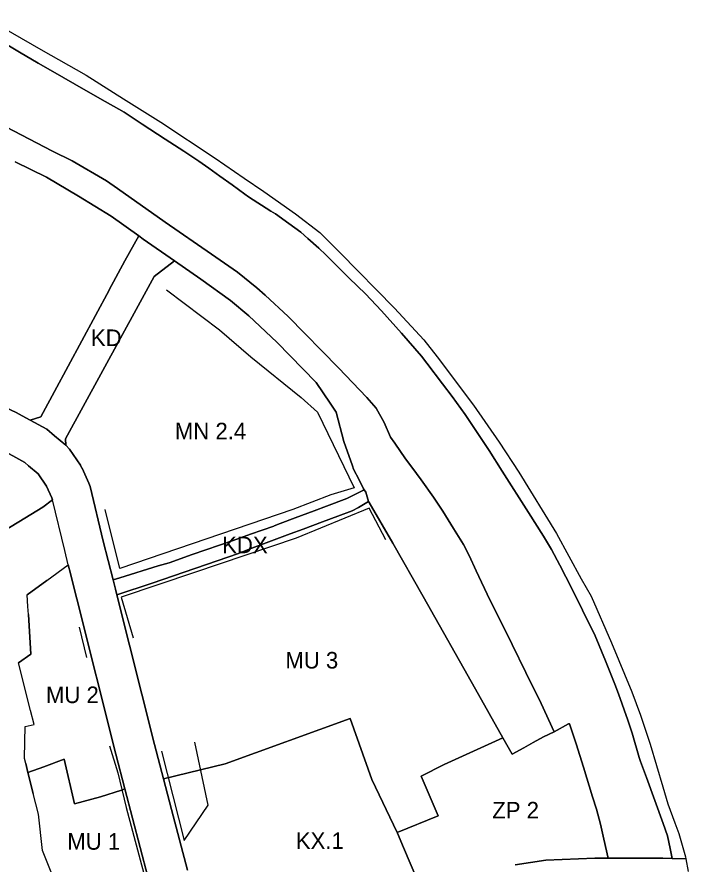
# Model space of a CAD drawing. Extents: x 7421359 to 7422386, y 5546414 to 5547388.
# Drawn here: x 7422151.6 to 7422354.4, y 5546861.7 to 5547117.5 of the extents above; entities that cross this region are included whole.
import ezdxf

# ---------------------------------------------------------------- set-up
doc = ezdxf.new("R2010")
doc.units = 0
for name, color, linetype in [('linie_rozgraniczajace', 7, 'Continuous'), ('linie_zabudowy', 7, 'Continuous'), ('oznaczenia_przeznaczen', 7, 'Continuous')]:
    doc.layers.add(name, color=color, linetype=linetype)

msp = doc.modelspace()

# ---------------------------------------------------------------- linework, layer by layer
at = {"layer": 'linie_rozgraniczajace'}
for points in [[(7422141.61, 5547117.54), (7422158.89, 5547107.72), (7422172.57, 5547099.93), (7422183.85, 5547092.84), (7422195.13, 5547085.76), (7422211.52, 5547074.84), (7422220.3, 5547068.87), (7422226.23, 5547064.84), (7422235.77, 5547058.08), (7422243.15, 5547052.42), (7422249.29, 5547046.25), (7422265.72, 5547029.57), (7422274.58, 5547020), (7422278.63, 5547014.87), (7422289.62, 5547000.29), (7422297.35, 5546989.09), (7422303.28, 5546980.06), (7422314.69, 5546961.52), (7422322.13, 5546947.79), (7422325.12, 5546942.62), (7422331.32, 5546928.5), (7422337.48, 5546913.66), (7422340.02, 5546906.62), (7422342.95, 5546897.93), (7422346.79, 5546884.98), (7422348.32, 5546879.88), (7422350.41, 5546874.14), (7422351.6, 5546870.88), (7422353.67, 5546863.88), (7422353.77, 5546863.31), (7422349.65, 5546863.38), (7422349.07, 5546866.36), (7422348.22, 5546870.17), (7422346.88, 5546873.99), (7422341.89, 5546887.8), (7422340.03, 5546892.64), (7422339.66, 5546893.83), (7422337.55, 5546901.2), (7422336.21, 5546905.11), (7422333.43, 5546913.11), (7422332.29, 5546916.03), (7422329.53, 5546923.07), (7422326.39, 5546930.64), (7422322.58, 5546938.38), (7422319.35, 5546944.93), (7422315.72, 5546952.01), (7422313.17, 5546956.68), (7422310.71, 5546960.77), (7422306.23, 5546967.89), (7422298.29, 5546980.38), (7422294.33, 5546986.61), (7422290.15, 5546992.91), (7422287.1, 5546997.42), (7422283.17, 5547002.86), (7422280.26, 5547006.75), (7422275.51, 5547013), (7422273.89, 5547015.11), (7422267.89, 5547022.03), (7422261.82, 5547028.73), (7422256.98, 5547033.91), (7422252.04, 5547038.69), (7422249.33, 5547041.36)], [(7422145.42, 5547110.99), (7422152.45, 5547106.92), (7422158.09, 5547103.62), (7422162.48, 5547101.09), (7422169.17, 5547097.24), (7422176.67, 5547092.95), (7422184.09, 5547088.74), (7422189.52, 5547085.16), (7422196.47, 5547080.62), (7422202.08, 5547076.96), (7422206.58, 5547073.97), (7422209.63, 5547071.91), (7422212.98, 5547069.5), (7422216.65, 5547066.82), (7422220.52, 5547064.06), (7422221.66, 5547063.22), (7422228.37, 5547058.91), (7422229.75, 5547058.04), (7422233.76, 5547055.14), (7422237.39, 5547052.56), (7422239.55, 5547050.65), (7422242.91, 5547047.73), (7422244.94, 5547045.73), (7422249.33, 5547041.36), (7422252.04, 5547038.69), (7422256.98, 5547033.91), (7422261.82, 5547028.73), (7422267.89, 5547022.03), (7422273.89, 5547015.11), (7422275.51, 5547013), (7422280.26, 5547006.75), (7422283.17, 5547002.86), (7422287.1, 5546997.42), (7422290.15, 5546992.91), (7422294.33, 5546986.61), (7422298.29, 5546980.38), (7422306.23, 5546967.89), (7422310.71, 5546960.77), (7422313.17, 5546956.68), (7422315.72, 5546952.01), (7422319.35, 5546944.93), (7422322.58, 5546938.38), (7422326.39, 5546930.64), (7422329.53, 5546923.07), (7422332.29, 5546916.03), (7422333.43, 5546913.11), (7422336.21, 5546905.11), (7422337.55, 5546901.2), (7422339.66, 5546893.83), (7422340.03, 5546892.64)], [(7422249.33, 5547041.36), (7422244.94, 5547045.73), (7422242.91, 5547047.73), (7422239.55, 5547050.65), (7422237.39, 5547052.56), (7422233.76, 5547055.14), (7422229.75, 5547058.04), (7422228.37, 5547058.91), (7422221.66, 5547063.22), (7422220.52, 5547064.06), (7422216.65, 5547066.82), (7422212.98, 5547069.5), (7422209.63, 5547071.91), (7422206.58, 5547073.97), (7422202.08, 5547076.96), (7422196.47, 5547080.62), (7422189.52, 5547085.16), (7422184.09, 5547088.74), (7422176.67, 5547092.95), (7422169.17, 5547097.24), (7422162.48, 5547101.09), (7422158.09, 5547103.62), (7422152.45, 5547106.92), (7422145.42, 5547110.99)], [(7422148.25, 5547084.32), (7422162.37, 5547077.03), (7422168.32, 5547074.05), (7422178.7, 5547068.04), (7422182.07, 5547065.68), (7422196.42, 5547055.53), (7422210.4, 5547045.85), (7422218.24, 5547040.45), (7422224.16, 5547035.69), (7422226.69, 5547033.53), (7422233.62, 5547027.02), (7422248.79, 5547011.55), (7422257.37, 5547002.6), (7422260.19, 5546999.38), (7422262.62, 5546995.07), (7422264.52, 5546990.6), (7422265.79, 5546988.77), (7422269.03, 5546984.13), (7422270.97, 5546981.52), (7422273.77, 5546977.7), (7422277.55, 5546972.48), (7422280.38, 5546968.24), (7422283.61, 5546963.04), (7422286.61, 5546958.2), (7422288.27, 5546954.89), (7422290.43, 5546950.25), (7422294.51, 5546941.52), (7422296.83, 5546936.93), (7422301.29, 5546927.98), (7422305.46, 5546919.53), (7422310.08, 5546910.23), (7422314, 5546901.62), (7422310.74, 5546900.15), (7422307.67, 5546898.44), (7422304.79, 5546896.82), (7422301.3, 5546894.88), (7422298.44, 5546899.77), (7422290.16, 5546914.51), (7422274.43, 5546942.53), (7422265.25, 5546958.66), (7422258.04, 5546970.93), (7422257.89, 5546971.17), (7422257.03, 5546973.99), (7422256.58, 5546974.7), (7422256.37, 5546975.04), (7422255.07, 5546977.76), (7422253.36, 5546980.94), (7422253, 5546981.96), (7422250.4, 5546989.31), (7422248.06, 5546998.18), (7422246.32, 5547000.85), (7422242.08, 5547007.18), (7422230.2, 5547019.28), (7422221.67, 5547027.27), (7422216.18, 5547031.95), (7422207.18, 5547038.34), (7422199.28, 5547043.84), (7422199.22, 5547043.88), (7422189.81, 5547050.47), (7422188.43, 5547051.46), (7422180.13, 5547057.36), (7422170.22, 5547063.45), (7422160.59, 5547069.15), (7422151.13, 5547073.79)], [(7422340.03, 5546892.64), (7422341.89, 5546887.8), (7422346.88, 5546873.99), (7422348.22, 5546870.17), (7422349.07, 5546866.36), (7422349.65, 5546863.38), (7422346.81, 5546863.43), (7422332.65, 5546863.51), (7422330.27, 5546863.48), (7422328.97, 5546869.22), (7422327.99, 5546873.73), (7422326.75, 5546878.29), (7422325.59, 5546882), (7422322.84, 5546890.95), (7422320.65, 5546898.01), (7422318.6, 5546904.07), (7422318.29, 5546904.05), (7422314, 5546901.62), (7422310.08, 5546910.23), (7422305.46, 5546919.53), (7422301.29, 5546927.98), (7422296.83, 5546936.93), (7422294.51, 5546941.52), (7422290.43, 5546950.25), (7422288.27, 5546954.89), (7422286.61, 5546958.2), (7422283.61, 5546963.04), (7422280.38, 5546968.24), (7422277.55, 5546972.48), (7422273.77, 5546977.7), (7422270.97, 5546981.52), (7422269.03, 5546984.13), (7422265.79, 5546988.77), (7422264.52, 5546990.6), (7422262.62, 5546995.07), (7422260.19, 5546999.38), (7422257.37, 5547002.6), (7422248.79, 5547011.55), (7422233.62, 5547027.02), (7422226.69, 5547033.53), (7422224.16, 5547035.69), (7422218.24, 5547040.45), (7422210.4, 5547045.85), (7422196.42, 5547055.53), (7422182.07, 5547065.68), (7422178.7, 5547068.04), (7422168.32, 5547074.05), (7422162.37, 5547077.03), (7422148.25, 5547084.32)], [(7422151.13, 5547073.79), (7422160.59, 5547069.15), (7422170.22, 5547063.45), (7422180.13, 5547057.36), (7422188.43, 5547051.46), (7422184.27, 5547043.83), (7422179.5, 5547035.1), (7422179.49, 5547035.08), (7422179.48, 5547035.07), (7422158.83, 5546996.73), (7422155.6, 5546995.77), (7422152.07, 5546997.69), (7422151.87, 5546997.78), (7422151.8, 5546997.83), (7422104.2, 5547020.58)], [(7422104.2, 5547020.58), (7422151.8, 5546997.83), (7422151.87, 5546997.78), (7422152.07, 5546997.69), (7422155.6, 5546995.77), (7422160.65, 5546993.08), (7422162.97, 5546991.04), (7422166.42, 5546988.19), (7422167.5, 5546986.99), (7422170.81, 5546982.15), (7422171.3, 5546981.28), (7422171.31, 5546981.27), (7422171.31, 5546981.26), (7422173.36, 5546976.77), (7422173.37, 5546976.75), (7422173.74, 5546975.69), (7422177.72, 5546959.26), (7422180.67, 5546947.56), (7422181.39, 5546944.68), (7422181.8, 5546943.05), (7422193.18, 5546897.85), (7422195.9, 5546887.48), (7422198.35, 5546878.17), (7422203.16, 5546859.84)], [(7422146.48, 5546987.07), (7422153.98, 5546982.99), (7422155.17, 5546981.99), (7422158.05, 5546979.55), (7422160.61, 5546975.8), (7422162.21, 5546972.3), (7422162.35, 5546971.73), (7422159.45, 5546969.45), (7422144.36, 5546960.37)], [(7422167.16, 5546952.08), (7422167.16, 5546952.08), (7422166.08, 5546956.36), (7422166.08, 5546956.39), (7422166.07, 5546956.41), (7422166.07, 5546956.41), (7422166.07, 5546956.41), (7422162.35, 5546971.73), (7422162.35, 5546971.73), (7422162.21, 5546972.3), (7422160.61, 5546975.8), (7422158.05, 5546979.55), (7422155.17, 5546981.99), (7422153.98, 5546982.99), (7422146.48, 5546987.07)], [(7422191.21, 5546857.83), (7422184.27, 5546884.46), (7422181.57, 5546894.85), (7422181.56, 5546894.87), (7422181.55, 5546894.9), (7422169.76, 5546941.75), (7422168.55, 5546946.53), (7422167.82, 5546949.45), (7422167.17, 5546952.02), (7422167.16, 5546952.08)], [(7422203.16, 5546859.84), (7422198.35, 5546878.17), (7422195.9, 5546887.48), (7422214.52, 5546891.96), (7422252.33, 5546905.7), (7422258.9, 5546887.24), (7422266.52, 5546871.21), (7422266.59, 5546871.07), (7422268.44, 5546866.74), (7422272.51, 5546857.25)], [(7422272.51, 5546857.25), (7422268.44, 5546866.74), (7422266.59, 5546871.07), (7422266.52, 5546871.21), (7422278.9, 5546876.29), (7422273.77, 5546888.29), (7422280.78, 5546891.79), (7422298.44, 5546899.77), (7422301.3, 5546894.88), (7422304.79, 5546896.82), (7422307.67, 5546898.44), (7422310.74, 5546900.15), (7422314, 5546901.62), (7422318.29, 5546904.05), (7422318.6, 5546904.07), (7422320.65, 5546898.01), (7422322.84, 5546890.95), (7422325.59, 5546882), (7422326.75, 5546878.29), (7422327.99, 5546873.73), (7422328.97, 5546869.22), (7422330.27, 5546863.48), (7422326.23, 5546863.43), (7422311.49, 5546862.83), (7422302.23, 5546861.43)], [(7422302.23, 5546861.43), (7422311.49, 5546862.83), (7422326.23, 5546863.43), (7422330.27, 5546863.48), (7422332.65, 5546863.51), (7422346.81, 5546863.43), (7422349.65, 5546863.38), (7422353.77, 5546863.31), (7422354.44, 5546859.47)]]:
    msp.add_lwpolyline(points, dxfattribs=at)
for points in [[(7422188.43, 5547051.46), (7422189.81, 5547050.47), (7422199.22, 5547043.88), (7422193.08, 5547039.1), (7422188.28, 5547030.32), (7422166.34, 5546990.11), (7422166.42, 5546988.19), (7422162.97, 5546991.04), (7422160.65, 5546993.08), (7422155.6, 5546995.77), (7422158.83, 5546996.73), (7422179.48, 5547035.07), (7422179.49, 5547035.08), (7422179.5, 5547035.1), (7422184.27, 5547043.83)], [(7422199.22, 5547043.88), (7422199.28, 5547043.84), (7422207.18, 5547038.34), (7422216.18, 5547031.95), (7422221.67, 5547027.27), (7422230.2, 5547019.28), (7422242.08, 5547007.18), (7422246.32, 5547000.85), (7422248.06, 5546998.18), (7422250.4, 5546989.31), (7422253, 5546981.96), (7422253.36, 5546980.94), (7422255.07, 5546977.76), (7422256.37, 5546975.04), (7422256.58, 5546974.7), (7422251.33, 5546972.07), (7422245.14, 5546969.75), (7422241.5, 5546968.41), (7422235.73, 5546966.24), (7422231.16, 5546964.5), (7422229.35, 5546963.81), (7422229.31, 5546963.76), (7422222.21, 5546961.28), (7422217, 5546959.41), (7422204.63, 5546955.18), (7422197.68, 5546952.72), (7422194.3, 5546951.75), (7422182.74, 5546948.17), (7422180.67, 5546947.56), (7422177.72, 5546959.26), (7422173.74, 5546975.69), (7422173.37, 5546976.75), (7422173.36, 5546976.77), (7422171.31, 5546981.26), (7422171.31, 5546981.27), (7422171.3, 5546981.28), (7422170.81, 5546982.15), (7422167.5, 5546986.99), (7422166.42, 5546988.19), (7422166.34, 5546990.11), (7422188.28, 5547030.32), (7422193.08, 5547039.1)], [(7422107.57, 5546974.79), (7422144.36, 5546960.37), (7422159.45, 5546969.45), (7422162.35, 5546971.73), (7422162.35, 5546971.73), (7422159.45, 5546969.45), (7422144.36, 5546960.37)], [(7422256.58, 5546974.7), (7422257.03, 5546973.99), (7422257.89, 5546971.17), (7422254.84, 5546969.34), (7422252.91, 5546968.38), (7422248.65, 5546966.79), (7422243.99, 5546965.02), (7422238.14, 5546962.84), (7422234.17, 5546961.39), (7422227.79, 5546959.01), (7422221.85, 5546956.78), (7422218.56, 5546955.45), (7422192.47, 5546946.53), (7422181.8, 5546943.05), (7422181.39, 5546944.68), (7422180.67, 5546947.56), (7422182.74, 5546948.17), (7422194.3, 5546951.75), (7422197.68, 5546952.72), (7422204.63, 5546955.18), (7422217, 5546959.41), (7422222.21, 5546961.28), (7422229.31, 5546963.76), (7422229.35, 5546963.81), (7422231.16, 5546964.5), (7422235.73, 5546966.24), (7422241.5, 5546968.41), (7422245.14, 5546969.75), (7422251.33, 5546972.07)], [(7422257.89, 5546971.17), (7422258.04, 5546970.93), (7422265.25, 5546958.66), (7422274.43, 5546942.53), (7422290.16, 5546914.51), (7422298.44, 5546899.77), (7422280.78, 5546891.79), (7422273.77, 5546888.29), (7422278.9, 5546876.29), (7422266.52, 5546871.21), (7422258.9, 5546887.24), (7422252.33, 5546905.7), (7422214.52, 5546891.96), (7422195.9, 5546887.48), (7422193.18, 5546897.85), (7422181.8, 5546943.05), (7422192.47, 5546946.53), (7422218.56, 5546955.45), (7422221.85, 5546956.78), (7422227.79, 5546959.01), (7422234.17, 5546961.39), (7422238.14, 5546962.84), (7422243.99, 5546965.02), (7422248.65, 5546966.79), (7422252.91, 5546968.38), (7422254.84, 5546969.34)], [(7422166.07, 5546956.41), (7422166.08, 5546956.39), (7422166.08, 5546956.36)], [(7422167.16, 5546952.08), (7422167.17, 5546952.02), (7422167.82, 5546949.45), (7422168.55, 5546946.53), (7422169.76, 5546941.75), (7422181.55, 5546894.9), (7422181.56, 5546894.87), (7422181.57, 5546894.85), (7422184.27, 5546884.46), (7422183.24, 5546884.04), (7422176.94, 5546882.01), (7422169.05, 5546879.93), (7422165.91, 5546893.36), (7422159.8, 5546891.1), (7422154.96, 5546889.37), (7422154.29, 5546892.03), (7422153.9, 5546893.59), (7422154.04, 5546898.68), (7422154.17, 5546903.2), (7422156.85, 5546903.88), (7422155.78, 5546908.1), (7422152.15, 5546922.44), (7422155.79, 5546925.05), (7422155.09, 5546937.03), (7422155.09, 5546937.03), (7422154.94, 5546939.5), (7422154.72, 5546942.96), (7422160.64, 5546947.3)], [(7422160.64, 5546947.3), (7422154.72, 5546942.96), (7422154.72, 5546942.96)], [(7422155.09, 5546937.03), (7422155.79, 5546925.05), (7422152.15, 5546922.44), (7422152.15, 5546922.44), (7422155.79, 5546925.05)], [(7422154.29, 5546892.03), (7422154.96, 5546889.37), (7422156.56, 5546882.99), (7422154.96, 5546889.37)], [(7422159.8, 5546891.1), (7422165.91, 5546893.36), (7422169.05, 5546879.93), (7422176.94, 5546882.01), (7422183.24, 5546884.04), (7422184.27, 5546884.46), (7422191.21, 5546857.83), (7422183.13, 5546851.79), (7422175.44, 5546845), (7422174.36, 5546844.11), (7422172.22, 5546846.73), (7422172.17, 5546846.8), (7422172.17, 5546846.8), (7422171.48, 5546847.56), (7422162.76, 5546857.26), (7422159.36, 5546865.74), (7422158.12, 5546876.77), (7422156.56, 5546882.99), (7422154.96, 5546889.37)]]:
    msp.add_lwpolyline(points, close=True, dxfattribs=at)
at = {"layer": 'linie_zabudowy'}
for points in [[(7422196.87, 5547035.14), (7422212.85, 5547023.07), (7422222.32, 5547014.85), (7422237.51, 5547002.63), (7422242.46, 5546998.19), (7422253.55, 5546975.31), (7422246.49, 5546973.17), (7422235.02, 5546968.73), (7422182.78, 5546950.99), (7422178.35, 5546968.81)], [(7422263.16, 5546959.58), (7422258.04, 5546969.14), (7422236, 5546960.07), (7422205.34, 5546949.79), (7422183.14, 5546942.26), (7422186.81, 5546929.97)], [(7422172.75, 5546924.1), (7422170.53, 5546933.28)], [(7422179.66, 5546897.37), (7422182.11, 5546889.27), (7422184.65, 5546878.78), (7422190.35, 5546857.38), (7422182.72, 5546851.59), (7422189.99, 5546842.62), (7422186.89, 5546837.46)], [(7422195.31, 5546895.81), (7422202.15, 5546868.8), (7422209.38, 5546879.46), (7422205.4, 5546898.46)]]:
    msp.add_lwpolyline(points, dxfattribs=at)

# ---------------------------------------------------------------- texts
at = {"layer": 'oznaczenia_przeznaczen'}
for s, p in [('KD', (7422173.985653, 5547018.150011)), ('MN 2.4', (7422199.366441, 5546989.970011)), ('KDX', (7422213.655988, 5546955.580011)), ('MU 3', (7422232.755182, 5546920.760011)), ('MU 2', (7422160.401378, 5546910.310011)), ('ZP 2', (7422295.263851, 5546875.470011)), ('MU 1', (7422166.857168, 5546866.030011)), ('KX.1', (7422235.916808, 5546866.260011))]:
    msp.add_text(s, height=4.999998, dxfattribs=at).set_placement(p)

doc.saveas('drawing.dxf')
